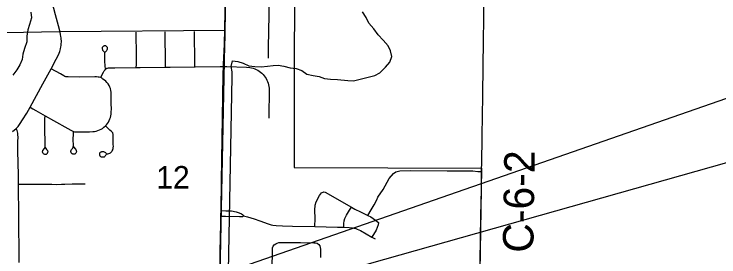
# Model space of a CAD drawing. Extents: x 0 to 42, y 0 to 22.
# Drawn here: x 5.866 to 7.178, y 17.821 to 18.271 of the extents above; entities that cross this region are included whole.
import ezdxf

# ---------------------------------------------------------------- set-up
doc = ezdxf.new("R2010")
doc.units = 0
for name, color, linetype in [('GM_X_City_Street', 7, 'Continuous'), ('GM_X_Corporation', 7, 'Continuous'), ('GM_X_County_Road', 7, 'Continuous'), ('GM_X_County_Road_Text', 7, 'Continuous'), ('GM_X_Interchange_Ramps', 7, 'Continuous'), ('GM_X_Minor_River', 7, 'Continuous'), ('GM_X_Section', 7, 'Continuous'), ('GM_X_Section_Text', 7, 'Continuous'), ('SH_Text', 7, 'Continuous')]:
    doc.layers.add(name, color=color, linetype=linetype)

msp = doc.modelspace()

# ---------------------------------------------------------------- linework, layer by layer
at = {"layer": 'GM_X_City_Street'}
for points in [[(6.3392, 18.1894), (6.3395, 18.2097), (6.342, 18.3322), (6.3425, 18.3585), (6.3435, 18.4175), (6.3436, 18.4268), (6.344, 18.4485)], [(6.0932, 18.1721), (6.0933, 18.1778), (6.0933, 18.1936), (6.0927, 18.2377)], [(6.1478, 18.1729), (6.1478, 18.1786), (6.1469, 18.2388)], [(6.202, 18.1736), (6.202, 18.1795), (6.202, 18.1921), (6.2015, 18.2268), (6.2015, 18.2392)], [(6.0363, 18.1699), (6.036, 18.1711), (6.0355, 18.1736), (6.0352, 18.1762), (6.0349, 18.1835), (6.0345, 18.1929), (6.0344, 18.196), (6.0345, 18.198), (6.0346, 18.1991), (6.0349, 18.2002), (6.0356, 18.2012), (6.0361, 18.2016), (6.0372, 18.2027), (6.0379, 18.2034), (6.0385, 18.2043), (6.0388, 18.2049), (6.0391, 18.2056), (6.0393, 18.2064), (6.0395, 18.2073), (6.0395, 18.2084), (6.0393, 18.2094), (6.0389, 18.2101), (6.0385, 18.2107), (6.038, 18.2112), (6.0372, 18.2119), (6.0363, 18.2123), (6.0356, 18.2125), (6.0349, 18.2126), (6.0337, 18.2125), (6.0325, 18.2122), (6.0319, 18.2119), (6.0307, 18.2108), (6.0302, 18.2101), (6.0299, 18.2093), (6.0297, 18.2084), (6.0297, 18.2074), (6.0297, 18.2067), (6.03, 18.2058), (6.0302, 18.2051), (6.0306, 18.2044), (6.0314, 18.2033), (6.032, 18.2026), (6.0345, 18.1999)], [(5.8953, 18.0985), (5.9007, 18.0955), (5.9062, 18.0925), (5.9237, 18.0824), (5.9388, 18.0741), (5.966, 18.0588), (5.9713, 18.0557), (5.9736, 18.0546), (5.976, 18.0535), (5.9779, 18.0531), (5.981, 18.0527), (5.9874, 18.0528), (6.006, 18.053), (6.0123, 18.0532), (6.0155, 18.0537), (6.0186, 18.0543), (6.0217, 18.0552), (6.0247, 18.0563), (6.0276, 18.0577), (6.0304, 18.0593), (6.033, 18.0612), (6.0358, 18.0637), (6.0376, 18.0656), (6.0395, 18.0682), (6.0412, 18.0709), (6.0427, 18.0737), (6.0439, 18.0767), (6.045, 18.0797), (6.0457, 18.0828), (6.0462, 18.0859), (6.0466, 18.0891), (6.0468, 18.0954), (6.0466, 18.1048), (6.0465, 18.1205), (6.0463, 18.1267), (6.046, 18.1296), (6.0451, 18.133), (6.044, 18.136), (6.0425, 18.139), (6.0406, 18.1417), (6.0384, 18.1444), (6.0362, 18.1468), (6.0339, 18.1487), (6.031, 18.1508), (6.0288, 18.1524), (6.027, 18.1535), (6.0242, 18.1544), (6.0222, 18.1546), (6.0191, 18.1548), (6.0159, 18.1549), (5.9878, 18.1546), (5.9663, 18.1548), (5.9643, 18.1548), (5.9633, 18.1549), (5.9625, 18.155), (5.9618, 18.1552), (5.9601, 18.1559), (5.9581, 18.157), (5.9521, 18.1604), (5.935, 18.1701)], [(6.027, 18.1535), (6.0297, 18.159), (6.0322, 18.1635), (6.0329, 18.1649), (6.0336, 18.166), (6.0342, 18.1669), (6.0351, 18.1682), (6.0363, 18.1699), (6.0382, 18.1708), (6.0398, 18.1713), (6.0413, 18.1716), (6.0441, 18.1717), (6.0534, 18.1716), (6.0932, 18.1721), (6.1002, 18.1722), (6.1478, 18.1729), (6.1563, 18.173), (6.202, 18.1736), (6.203, 18.1736), (6.2496, 18.1742), (6.2558, 18.174), (6.2595, 18.174), (6.2615, 18.1739), (6.2986, 18.1732), (6.3048, 18.1726), (6.3079, 18.172), (6.3109, 18.1711), (6.3138, 18.17), (6.3167, 18.1687), (6.3195, 18.1672), (6.3221, 18.1655), (6.3246, 18.1636), (6.327, 18.1615), (6.3292, 18.1593), (6.3313, 18.1569), (6.3331, 18.1543), (6.3348, 18.1517), (6.3363, 18.1489), (6.3376, 18.146), (6.3387, 18.1431), (6.3395, 18.14), (6.3401, 18.137), (6.3405, 18.1338), (6.3407, 18.1276), (6.3399, 18.0845), (6.34, 18.0781)], [(5.9234, 18.0238), (5.9263, 18.0199), (5.9272, 18.0187), (5.9276, 18.0181), (5.9279, 18.0175), (5.9282, 18.0163), (5.9283, 18.0154), (5.9281, 18.0144), (5.9279, 18.0136), (5.9275, 18.0129), (5.9272, 18.0123), (5.9267, 18.0117), (5.926, 18.0112), (5.9253, 18.0109), (5.9245, 18.0107), (5.9236, 18.0106), (5.9228, 18.0107), (5.9214, 18.0111), (5.9205, 18.0117), (5.9198, 18.0125), (5.9192, 18.0135), (5.9189, 18.0143), (5.9187, 18.015), (5.9187, 18.0157), (5.9187, 18.0165), (5.9189, 18.0173), (5.9193, 18.018), (5.9224, 18.022), (5.9229, 18.0229), (5.9231, 18.0235), (5.9233, 18.0244), (5.9235, 18.0252), (5.9235, 18.026), (5.9232, 18.0639), (5.923, 18.0724), (5.9232, 18.0771), (5.9237, 18.0824)], [(5.8625, 18.0537), (5.8693, 18.0589)], [(6.0379, 18.0117), (6.0365, 18.0094), (6.0355, 18.008), (6.0347, 18.0069), (6.034, 18.0063), (6.0335, 18.006), (6.0327, 18.0057), (6.032, 18.0055), (6.0307, 18.0055), (6.0296, 18.0056), (6.0289, 18.0057), (6.0282, 18.006), (6.0274, 18.0065), (6.0268, 18.007), (6.0262, 18.0075), (6.0257, 18.0084), (6.0254, 18.009), (6.0252, 18.0101), (6.0252, 18.012), (6.0253, 18.0128), (6.0256, 18.0137), (6.0262, 18.0146), (6.0267, 18.015), (6.0276, 18.0156), (6.0283, 18.0159), (6.0291, 18.0162), (6.0301, 18.0164), (6.0312, 18.0163), (6.0322, 18.0161), (6.0334, 18.0158), (6.0347, 18.015), (6.0357, 18.0143), (6.0366, 18.0135), (6.0372, 18.0128), (6.0383, 18.0122), (6.0392, 18.0121), (6.0404, 18.0121), (6.0421, 18.0124), (6.0438, 18.0132), (6.0451, 18.014), (6.0467, 18.0153), (6.0476, 18.0163), (6.0486, 18.0177), (6.0493, 18.0192), (6.0498, 18.0203), (6.0501, 18.0214), (6.0503, 18.0224), (6.0504, 18.0241), (6.0505, 18.0256), (6.0504, 18.0294), (6.0504, 18.0361), (6.0503, 18.0441), (6.0502, 18.0458), (6.0501, 18.047), (6.05, 18.0484), (6.0497, 18.0498), (6.0494, 18.0507), (6.0489, 18.0514), (6.0483, 18.0523), (6.0477, 18.0529), (6.0463, 18.0541), (6.0441, 18.056), (6.0401, 18.0595), (6.0358, 18.0637)], [(5.9762, 18.025), (5.98, 18.0208), (5.9804, 18.0202), (5.9808, 18.0195), (5.9811, 18.0188), (5.9814, 18.018), (5.9815, 18.0172), (5.9816, 18.0163), (5.9816, 18.0154), (5.9813, 18.0142), (5.9806, 18.0129), (5.9802, 18.0125), (5.9797, 18.012), (5.9789, 18.0116), (5.9783, 18.0114), (5.9776, 18.0113), (5.9768, 18.0113), (5.9753, 18.0115), (5.9745, 18.0117), (5.9739, 18.012), (5.9732, 18.0125), (5.9726, 18.013), (5.9722, 18.0137), (5.9718, 18.0144), (5.9717, 18.0151), (5.9716, 18.0159), (5.9716, 18.0173), (5.9718, 18.0181), (5.9722, 18.0188), (5.9727, 18.0198), (5.9732, 18.0205), (5.974, 18.0214), (5.9748, 18.0224), (5.9752, 18.0232), (5.9755, 18.0239), (5.9758, 18.0246), (5.9759, 18.0252), (5.9761, 18.0269), (5.9759, 18.0391), (5.976, 18.0483), (5.976, 18.0535)], [(6.5245, 17.8971), (6.5307, 17.9079), (6.5363, 17.9174), (6.5409, 17.9263), (6.5431, 17.9314), (6.5528, 17.9456), (6.564, 17.9661), (6.572, 17.9752), (6.5767, 17.9786), (6.5841, 17.9802), (6.604, 17.9807), (6.6722, 17.9806), (6.7197, 17.9803), (6.7293, 17.9794), (6.7362, 17.9789)], [(5.8737, 17.9555), (5.8793, 17.9554), (5.8954, 17.9553), (5.9173, 17.9556), (5.9359, 17.9556), (5.9448, 17.9551), (5.9538, 17.9554), (5.96, 17.9558), (5.9737, 17.9559), (5.9854, 17.956), (5.9981, 17.956)], [(6.4255, 17.8767), (6.4261, 17.8915), (6.4256, 17.9072), (6.4264, 17.9167), (6.428, 17.923), (6.4342, 17.9344), (6.4383, 17.9397), (6.4422, 17.9415), (6.445, 17.9408), (6.4941, 17.9126), (6.5002, 17.9094), (6.5106, 17.904), (6.5245, 17.8971), (6.5302, 17.8947), (6.5386, 17.8888), (6.5444, 17.8846), (6.5438, 17.8798), (6.5399, 17.8703), (6.532, 17.8572)], [(6.2513, 17.9066), (6.26, 17.9063), (6.2658, 17.9063), (6.2687, 17.906), (6.2706, 17.9059), (6.2733, 17.9055), (6.2758, 17.905), (6.2792, 17.904), (6.2847, 17.9022), (6.2892, 17.9004), (6.2908, 17.8993), (6.2916, 17.8987), (6.2926, 17.8975), (6.2929, 17.8967)], [(6.4794, 17.8756), (6.4797, 17.8822), (6.4801, 17.8876), (6.4815, 17.8915), (6.4847, 17.898), (6.4902, 17.9072), (6.4941, 17.9126)], [(6.251, 17.8962), (6.2595, 17.8961), (6.2856, 17.8956), (6.2887, 17.8955), (6.29, 17.8956), (6.2909, 17.8958), (6.2929, 17.8967)], [(6.2929, 17.8967), (6.3002, 17.8952), (6.3124, 17.8914), (6.3232, 17.8876), (6.3386, 17.8818), (6.3445, 17.8801), (6.3474, 17.8794), (6.3534, 17.8786), (6.3657, 17.878), (6.3843, 17.8775), (6.4255, 17.8767), (6.4677, 17.876), (6.4794, 17.8756), (6.4894, 17.8753), (6.4956, 17.8746), (6.4987, 17.874), (6.5018, 17.8731), (6.5047, 17.872), (6.5104, 17.8694), (6.5213, 17.8633), (6.532, 17.8572), (6.538, 17.8538)], [(6.3463, 17.7967), (6.3469, 17.834), (6.3471, 17.8372), (6.348, 17.8404), (6.35, 17.8431), (6.3528, 17.845), (6.3558, 17.8462), (6.3589, 17.847), (6.3622, 17.8473), (6.396, 17.847), (6.3991, 17.8472), (6.4238, 17.8466), (6.427, 17.8465), (6.4302, 17.8458), (6.4331, 17.8438), (6.435, 17.841), (6.4359, 17.8378), (6.4361, 17.8346), (6.436, 17.8253), (6.436, 17.8191)]]:
    msp.add_lwpolyline(points, dxfattribs=at)
at = {"layer": 'GM_X_Corporation'}
for points in [[(6.388, 18.4919), (6.3873, 17.9866), (6.7361, 17.9852), (6.7327, 17.7925)], [(5.3129, 18.3855), (5.308, 18.2653), (5.3792, 18.2639), (5.3792, 18.2301), (5.4084, 18.2295), (5.951, 18.2391), (6.2578, 18.2418), (6.26, 18.3342)]]:
    msp.add_lwpolyline(points, dxfattribs=at)
at = {"layer": 'GM_X_County_Road'}
msp.add_line((6.2581, 18.2423), (6.2602, 18.3336), dxfattribs=at)
for points in [[(5.9513, 18.2386), (5.9509, 18.2406), (5.9486, 18.2495), (5.943, 18.2701), (5.9341, 18.3034), (5.9307, 18.3166), (5.9161, 18.3708), (5.8927, 18.4578), (5.8869, 18.4819), (5.8867, 18.4837)], [(6.7363, 17.9846), (6.7365, 17.9926), (6.737, 18.0454), (6.7383, 18.1199), (6.7389, 18.1758), (6.7408, 18.3094), (6.7431, 18.474), (6.7429, 18.4872)], [(6.2558, 18.174), (6.2558, 18.1775), (6.258, 18.2272), (6.258, 18.2413), (6.2581, 18.2423)], [(5.8953, 18.0985), (5.9191, 18.1421), (5.935, 18.1701), (5.944, 18.1876), (5.947, 18.1935), (5.9494, 18.1987), (5.9507, 18.202), (5.9515, 18.2047), (5.9521, 18.2072), (5.9528, 18.2105), (5.9532, 18.2134), (5.9535, 18.2162), (5.9537, 18.2197), (5.9537, 18.2221), (5.9535, 18.2247), (5.9533, 18.2266), (5.9527, 18.2305), (5.9523, 18.2331), (5.9513, 18.2386)], [(6.251, 17.8962), (6.2513, 17.9066), (6.252, 17.9598), (6.2526, 18.0002), (6.2538, 18.078), (6.2554, 18.1588), (6.2558, 18.174)], [(5.8693, 18.0589), (5.873, 18.0629), (5.8771, 18.0684), (5.8811, 18.075), (5.8891, 18.0877), (5.8953, 18.0985)], [(5.8737, 17.9555), (5.8737, 17.9728), (5.8729, 18.0166), (5.8729, 18.0352), (5.873, 18.0422), (5.8729, 18.048), (5.8728, 18.0504), (5.8723, 18.0526), (5.8714, 18.055), (5.8693, 18.0589)], [(6.733, 17.793), (6.7333, 17.8125), (6.7347, 17.8964), (6.7357, 17.9461), (6.7362, 17.9777), (6.7362, 17.9789), (6.7363, 17.9846)], [(5.8752, 17.8099), (5.8753, 17.8231), (5.8751, 17.8476), (5.8747, 17.8625), (5.8748, 17.8718), (5.8744, 17.8966), (5.8742, 17.9214), (5.8737, 17.9277), (5.874, 17.933), (5.8741, 17.9359), (5.8738, 17.9481), (5.8737, 17.9555)], [(6.2483, 17.7336), (6.25, 17.8292), (6.2508, 17.8821), (6.251, 17.8962)]]:
    msp.add_lwpolyline(points, dxfattribs=at)
at = {"layer": 'GM_X_Interchange_Ramps'}
for points in [[(6.2481, 17.7341), (6.2497, 17.8297), (6.2506, 17.8826), (6.2508, 17.8968), (6.2511, 17.9072), (6.2517, 17.9604), (6.2523, 18.0008), (6.2535, 18.0785), (6.2552, 18.1594), (6.2555, 18.1746), (6.2556, 18.1781), (6.2578, 18.2278), (6.2578, 18.2418), (6.26, 18.3342)], [(6.26, 18.3342), (6.2578, 18.2418), (6.2578, 18.2278), (6.2556, 18.1781), (6.2555, 18.1746), (6.2552, 18.1594), (6.2535, 18.0785), (6.2523, 18.0008), (6.2517, 17.9604), (6.2511, 17.9072), (6.2508, 17.8968), (6.2506, 17.8826), (6.2497, 17.8297), (6.2481, 17.7341)]]:
    msp.add_lwpolyline(points, dxfattribs=at)
at = {"layer": 'GM_X_Minor_River'}
for points in [[(5.8966, 18.2754), (5.8979, 18.2647), (5.8946, 18.2519), (5.8913, 18.2421), (5.8891, 18.2304), (5.8892, 18.2201), (5.8852, 18.2077), (5.8819, 18.1971), (5.8805, 18.1873), (5.8761, 18.1775), (5.8706, 18.1678), (5.8635, 18.1581)], [(6.2718, 18.1547), (6.272, 18.1641), (6.2696, 18.1741), (6.2724, 18.1846), (6.2823, 18.1837), (6.2924, 18.1804), (6.3025, 18.1753), (6.3139, 18.1739), (6.326, 18.1737), (6.3374, 18.175), (6.348, 18.1763), (6.3575, 18.1769), (6.3681, 18.1751), (6.3798, 18.1719), (6.3907, 18.1705), (6.4012, 18.1665), (6.411, 18.1602), (6.4223, 18.1573), (6.4336, 18.1556), (6.4434, 18.1516), (6.4547, 18.1506), (6.468, 18.1503), (6.4869, 18.1484), (6.4979, 18.1478), (6.5074, 18.1499), (6.5173, 18.1524), (6.5276, 18.1548), (6.5371, 18.1573), (6.547, 18.1624), (6.5571, 18.1728), (6.5656, 18.1825), (6.5692, 18.1927), (6.5668, 18.203), (6.5621, 18.2126), (6.5532, 18.223), (6.5435, 18.2331), (6.5358, 18.2443), (6.5265, 18.2547), (6.5214, 18.2654), (6.5145, 18.2758)], [(6.2623, 17.6628), (6.2718, 18.1547)]]:
    msp.add_lwpolyline(points, dxfattribs=at)
at = {"layer": 'GM_X_Section'}
for points in [[(5.2524, 18.4847), (6.2631, 18.4885), (6.2427, 17.4846), (5.2334, 17.4797)], [(6.2631, 18.4885), (7.2453, 18.4817), (7.2316, 17.475), (6.2427, 17.4846)]]:
    msp.add_lwpolyline(points, close=True, dxfattribs=at)
at = {"layer": 'SH_Text'}
msp.add_lwpolyline([(9.439, 18.8951), (5.359, 17.4787), (9.439, 18.63)], close=True, dxfattribs=at)

# ---------------------------------------------------------------- texts
at = {"layer": 'GM_X_County_Road_Text'}
msp.add_text('C-6-2', height=0.05682, rotation=89.1132, dxfattribs=at).set_placement((6.8324, 17.8279))
at = {"layer": 'GM_X_Section_Text'}
msp.add_text('12', height=0.04186, rotation=0, dxfattribs=at).set_placement((6.1304, 17.9474))

doc.saveas('drawing.dxf')
